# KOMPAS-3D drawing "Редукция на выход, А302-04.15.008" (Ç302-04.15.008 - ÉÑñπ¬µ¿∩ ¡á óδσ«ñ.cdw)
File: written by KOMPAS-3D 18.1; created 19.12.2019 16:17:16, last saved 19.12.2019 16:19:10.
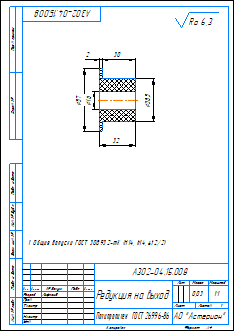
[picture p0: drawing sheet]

Sheet 1: A4, portrait

Document properties: Полное имя файла: D:\Мембранные насосы\Мембранный электропривод\А302-00.00.000 - ASTRA-302 (МЭ200)\А302-04.00.000 - Мембранный насос ASTRA-302-PP\А302-04.15.008 - Редукция на выход.cdw; Параметр неуказанной шероховатости: Ra 6,3; Масса: 0.0302348

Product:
- Part/product: Редукция на выход  | designation А302-04.15.008
    Материал: Полипропилен  ГОСТ 26996-86 (density 900 kg/m3)
    Масса: 0.0302348

Title block, sheet 1: Наименование: Редукция на выход; designation: А302-04.15.008; Материал: Полипропилен  ГОСТ 26996-86; Масса: 0,03; Количество листов документа: 1; organisation: АО "Астерион"; Форматы листов документа: A4; Разработал: Лифлянд

Views: Проекционный вид 3, Местный разрез 1
Referenced files in D:\Мембранные насосы\Мембранный электропривод\А302-00.00.000 - ASTRA-302 (МЭ200)\А302-04.00.000 - Мембранный насос ASTRA-302-PP\: А302-04.15.008 - Редукция на выход.m3d
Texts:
  Ra 6,3
Dimensions and other numbers on the sheet: 32; 57; 16; 38,5; 30; 2; 1:1; 1; 0,03

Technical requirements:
  Общие допуски ГОСТ 30893.2-mK (H14, h14,  t2/2).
